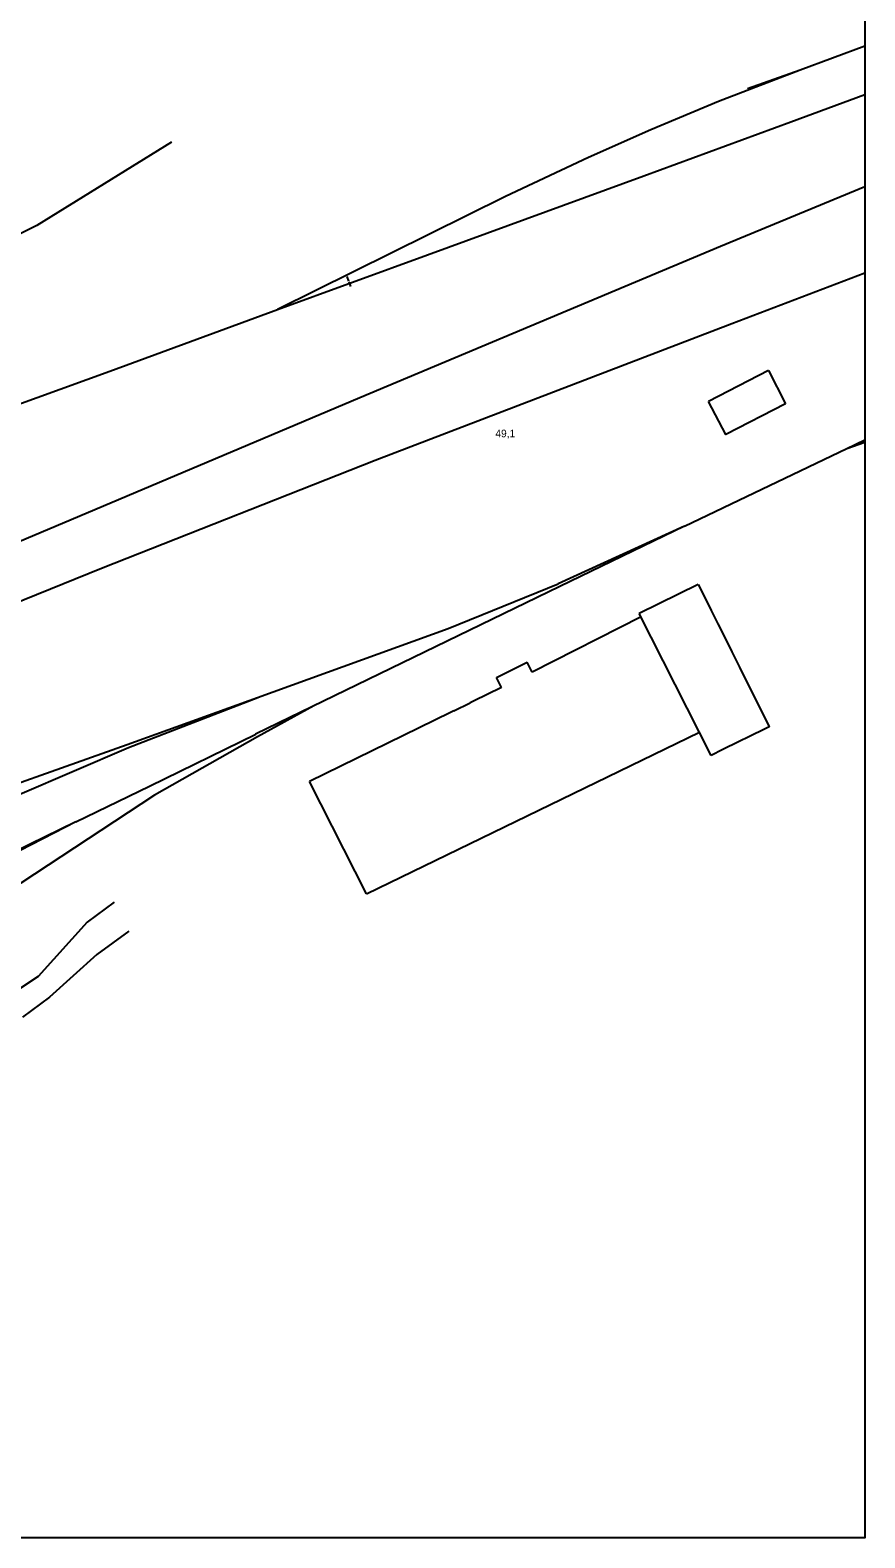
# Model space of a CAD drawing. Extents: x -760612 to 3170, y -975740 to 2995.
# Drawn here: x 1640.2 to 1804.3, y 1584.3 to 1881 of the extents above; entities that cross this region are included whole.
import ezdxf

# ---------------------------------------------------------------- set-up
doc = ezdxf.new("R2010")
doc.units = 0
for name, color, linetype in [('Border', 7, 'Continuous'), ('Implicitní', 7, 'Continuous'), ('Koleje_stávající', 7, 'Continuous'), ('Komunikace_stávající', 7, 'Continuous'), ('Objekty_stávající', 7, 'Continuous'), ('SL_05_KOMUNIKACE', 7, 'Continuous')]:
    doc.layers.add(name, color=color, linetype=linetype)

# ---------------------------------------------------------------- blocks, each defined once
blk = doc.blocks.new('5.121_1')
at = {"layer": 'Implicitní'}
blk.add_line((0, 0), (0, 0.005), dxfattribs=at)
blk = doc.blocks.new('přehledka_1')
at = {"layer": 'Border'}
blk.add_lwpolyline([(0, 0), (0.99915, 0), (0.99915, -0.65218), (0, -0.65218)], close=True, dxfattribs=at)
at = {"layer": 'Koleje_stávající'}
for p, q in [((0.98646, -0.3634), (0.97605, -0.36709)), ((0.96368, -0.45312), (0.99561, -0.43783)), ((0.99551, -0.43788), (0.99915, -0.43611))]:
    blk.add_line(p, q, dxfattribs=at)
for points in [[(0.99915, -0.35871), (0.98646, -0.3634), (0.97038, -0.3696), (0.9571, -0.37516), (0.9448, -0.3806), (0.92852, -0.38824), (0.88366, -0.4105)], [(0.70214, -0.47688), (0.73116, -0.46624), (0.75926, -0.45598), (0.79086, -0.44442), (0.82654, -0.43138), (0.85068, -0.4226), (0.88366, -0.4105), (0.91314, -0.39974), (0.9557, -0.38422), (0.9846, -0.37358), (0.99915, -0.36822)], [(0.34457, -0.65218), (0.36094, -0.6463), (0.42022, -0.62434), (0.46232, -0.60838), (0.53854, -0.5786), (0.57568, -0.5638), (0.66464, -0.52712), (0.72204, -0.50292), (0.78868, -0.4748), (0.8431, -0.45184), (0.89984, -0.4278), (0.97074, -0.39804), (0.99915, -0.38627)], [(0.3708, -0.65218), (0.4231, -0.6328), (0.4657, -0.61666), (0.54136, -0.5872), (0.66806, -0.53566), (0.72606, -0.51164), (0.79336, -0.48394), (0.84902, -0.46136), (0.90286, -0.44012), (0.973, -0.41326), (0.99915, -0.40329)], [(0.9956, -0.43784), (0.99915, -0.43657)], [(0.96369, -0.45311), (0.9392, -0.46503), (0.87936, -0.49405)], [(0.96368, -0.45311), (0.93888, -0.46448)], [(0.93882, -0.46451), (0.91721, -0.4733), (0.87973, -0.48691)], [(0.87976, -0.4869), (0.85436, -0.49675), (0.833, -0.50595), (0.7568, -0.54149), (0.69227, -0.57414)], [(0.89083, -0.48849), (0.87974, -0.49455), (0.85947, -0.50608), (0.79133, -0.55094)], [(0.87973, -0.48691), (0.8541, -0.49617), (0.81712, -0.50929)], [(0.84401, -0.51131), (0.85851, -0.50427), (0.87937, -0.49405)], [(0.84401, -0.51131), (0.81958, -0.52321), (0.78416, -0.54033), (0.75967, -0.55229), (0.70542, -0.57871), (0.65749, -0.60528), (0.59036, -0.65218)], [(0.84401, -0.51131), (0.8199, -0.52367), (0.7512, -0.56635), (0.672, -0.61933)]]:
    blk.add_lwpolyline(points, dxfattribs=at)
at = {"layer": 'Komunikace_stávající'}
for points in [[(0.86278, -0.37758), (0.83634, -0.39394), (0.82248, -0.40084), (0.81559, -0.40377), (0.7832, -0.4125), (0.753, -0.42404), (0.7175, -0.43768), (0.67214, -0.4551), (0.6388, -0.4677), (0.63028, -0.47065), (0.6121, -0.47734), (0.56748, -0.49352), (0.52088, -0.51014), (0.49772, -0.51898), (0.48486, -0.5233), (0.47346, -0.527), (0.43028, -0.54132), (0.38862, -0.5539), (0.36736, -0.5607), (0.36645, -0.56105)], [(0.85156, -0.5271), (0.8462, -0.53106), (0.8366, -0.54176), (0.80928, -0.55976)], [(0.85442, -0.53284), (0.8481, -0.53742), (0.83884, -0.54582), (0.83348, -0.54974)]]:
    blk.add_lwpolyline(points, dxfattribs=at)
at = {"layer": 'Objekty_stávající'}
for p, q in [((0.98023, -0.42251), (0.9684, -0.42858)), ((0.98023, -0.42251), (0.98358, -0.42904)), ((0.95514, -0.47099), (0.93372, -0.48183)), ((0.93372, -0.48183), (0.93278, -0.4799)), ((0.92768, -0.48489), (0.9267, -0.48288)), ((0.90116, -0.52546), (0.96662, -0.49367))]:
    blk.add_line(p, q, dxfattribs=at)
for points in [[(0.98358, -0.42904), (0.97184, -0.43506), (0.9684, -0.42858)], [(0.9664, -0.4646), (0.95478, -0.47028)], [(0.9664, -0.4646), (0.96742, -0.46665), (0.96896, -0.46974), (0.97026, -0.47235), (0.9718, -0.47545), (0.973, -0.47785), (0.9745, -0.48087), (0.98034, -0.49258), (0.97953, -0.49298), (0.97644, -0.49451), (0.97431, -0.49556), (0.97124, -0.49707), (0.96892, -0.49822)], [(0.96892, -0.49822), (0.95478, -0.47028)], [(0.9267, -0.48288), (0.93278, -0.4799)], [(0.92768, -0.48489), (0.9222, -0.48757), (0.92157, -0.48788)], [(0.91835, -0.48945), (0.91767, -0.48978), (0.88998, -0.50334)], [(0.91835, -0.48945), (0.92157, -0.48788)], [(0.90116, -0.52546), (0.88998, -0.50334)]]:
    blk.add_lwpolyline(points, dxfattribs=at)
at = {"layer": 'Koleje_stávající', "xscale": 0.2, "yscale": 0.20000000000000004, "rotation": 19.393445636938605}
for p in [(0.8977, -0.40493), (0.89808, -0.40599)]:
    blk.add_blockref('5.121_1', p, dxfattribs=at)
at = {"layer": 'Koleje_stávající'}
blk.add_text('49,1', height=0.0015, dxfattribs=at).set_placement((0.9265, -0.43564))

msp = doc.modelspace()

# ---------------------------------------------------------------- block references
at = {"layer": 'SL_05_KOMUNIKACE', "xscale": 999.99914, "yscale": 999.99914}
msp.add_blockref('přehledka_1', (805.17, 2236.5), dxfattribs=at)

doc.saveas('drawing.dxf')
